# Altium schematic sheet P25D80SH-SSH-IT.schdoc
size 127 x 101 mm
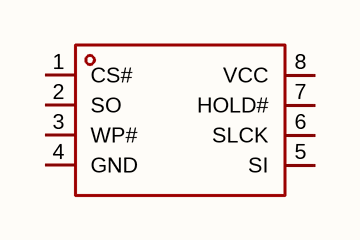
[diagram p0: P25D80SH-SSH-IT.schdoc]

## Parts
U?  p25d80sh-ssh-it  [SOP-8_L4.9-W3.9-P1.27-LS6.0-BL-1]  (value not drawn)

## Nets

Not connected (* = marked no-connect by the designer): U? 1(CS#) 2(SO) 3(WP#) 4(GND) 5(SI) 6(SLCK) 7(HOLD#) 8(VCC)

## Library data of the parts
U? = p25d80sh-ssh-it: 接口类型:SPI;存储容量:8Mbit;时钟频率(fc):120MHz;; Manufacturer: PUYA(普冉); AddInBom: yes; ModelId: 75c24a7891ee4dd6bdac16a7163ff87e; ModelTransform: 192.913,236.22,0,0,0,0,0,0,0; Interface: SPI; Memory Size: 8Mbit; Clock Frequency: 120MHz; Voltage - Supply: 2.3V~3.6V; Standby Supply Current: 20uA; Program / Erase Cycles: 100000次; Write Cycle Time (tWC): 12ms; Page Programming Time (Tpp): 3ms; Data Retention - TDR (Year): 10年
